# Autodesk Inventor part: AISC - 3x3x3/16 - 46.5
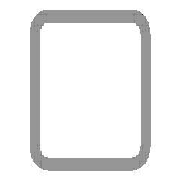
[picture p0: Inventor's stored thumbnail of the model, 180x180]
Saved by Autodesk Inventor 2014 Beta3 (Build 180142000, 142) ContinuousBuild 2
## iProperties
IsCustomPart: 1
Created: 2011-01
Part Number: AISC - 3x3x3/16 - 46.5
Material: Steel, Mild
Description: Tube
Document SubType Name: Modeling
Standard: ANSI
Designer: Beta-8540w
Standards Organization: ANSI
Language: en-US
Size Designation: 3x3x3/16
Categories: <MemberInstance><Categories><Category DisplayName="Structural Shapes" InternalName="089c4875-fa83-4c05-b084-43b9cc11f5ed" Mnemonic="GRDR"><CategoryParameter Dis
Stock Number: 3x3x3/16
Density: 7.86 g/cm^3
Appearance: Steel
_CCFamilyMember: 9
_CCFamilyDisplayName: ANSI AISC (Square) - Tube
_FrameMemberDoc: Frame Member File
_Version: 15.0.0
_GetPNFromCC: 1
G_W: 3.000 in
G_H: 3.000 in
G_L: 46.500 in
+C42BEBB0-0B1A-4817-9F77-B09BD408BF7C+CUTDETAIL2: Notch
Author: Beta-8540w
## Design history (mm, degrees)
node "Start plane"
node "End plane"
sketch "Sketch"
  geometry: L1 (-38.1, -28.575)-(-38.1, 28.575); L2 (-28.575, 38.1)-(28.575, 38.1); L3 (38.1, 28.575)-(38.1, -28.575); L4 (28.575, -38.1)-(-28.575, -38.1); L5 (-28.575, 33.337)-(28.575, 33.338); L6 (33.338, 28.575)-(33.338, -28.575); L7 (28.575, -33.337)-(-28.575, -33.338); L8 (-33.338, -28.575)-(-33.338, 28.575); L9 (0, 56.102)-(0, -56.102) reference; L10 (-56.102, 0)-(56.102, 0) reference; A1 r 9.525 centre (-28.575, -28.575) between (-38.1, -28.575) and (-28.575, -38.1); A2 r 9.525 centre (-28.575, 28.575) between (-28.575, 38.1) and (-38.1, 28.575); A3 r 9.525 centre (28.575, 28.575) between (38.1, 28.575) and (28.575, 38.1); A4 r 9.525 centre (28.575, -28.575) between (28.575, -38.1) and (38.1, -28.575); A5 r 4.763 centre (-28.575, 28.575) between (-28.575, 33.337) and (-33.338, 28.575); A6 r 4.763 centre (28.575, 28.575) between (33.338, 28.575) and (28.575, 33.338); A7 r 4.763 centre (28.575, -28.575) between (28.575, -33.337) and (33.338, -28.575); A8 r 4.763 centre (-28.575, -28.575) between (-33.338, -28.575) and (-28.575, -33.338)
  constraints: 16 end point, 16 point on circle, 8 centre point, 8 tangent, 4 parallel, 3 equal radius, 2 perpendicular, 7 other
  dimensions: "d10" = 76.2 distance between parallel lines of L2 L4 (= G_H); "d11" = 76.2 distance between parallel lines of L1 L3 (= G_W); "d12" = 4.7625 distance between parallel lines of L3 L6 (= G_T); "d15" = 38.1 distance between parallel lines of L2 L10 (= 0.5 x d10); "d16" = 38.1 distance between parallel lines of L9 L3 (= 0.5 x d11); "d17" = 9.525 radius of A1 (= G_IR)
extrude "Body" new body sketch "Sketch" stored distance "d3" = 1181.1 (= G_L); taper "d4" = 0 deg
node "Driven Length"
  sketch "Sketch3"
    geometry: L1 (0, 0)-(10, 0) reference
    constraints: 2 end point, 1 horizontal
  workplane "Work Plane3"
  sketch "Sketch4"
    geometry: L1 (-2, 38.1)-(12, 38.1) reference; L2 (-2, 1219.2)-(12, 1219.2) reference
    dimensions: "d19" = 1181.1 distance between parallel lines of L1 L2 (derived)
workplane "Work Plane4"
split "Split1"
body "Solid1"
feature "Sculpt1"
combine "Combine1"
body "Srf11"
body "Srf12"
body "Solid5"
feature "Surface1"
body "Srf10"
patch "Boundary Patch7" dims "d76" = 5, "d77" = 5, "d78" = 5, "d79" = 5, "d80" = 5, "d81" = 5, "d82" = 5, "d83" = 5, "d84" = 0
patch "Boundary Patch8" dims "d85" = 5, "d86" = 5, "d87" = 5, "d88" = 5, "d89" = 5, "d90" = 5, "d91" = 5, "d92" = 5, "d93" = 0
other parameters: "G_W" = 76.2 [user parameter; used in 1 equation term], "G_H" = 76.2 [user parameter; used in 1 equation term], "G_T" = 4.7625 [user parameter; used in 1 equation term], "G_IR" = 9.525 [user parameter; used in 1 equation term], "G_L" = 1181.1 (= d19) [user parameter; used in 1 equation term], "G_OFFSET_START" = -38.1 [user parameter; used in 1 equation term], "G_OFFSET_END" = 0 [user parameter; used in 1 equation term], "d13" = 38.1 (= -G_OFFSET_START), "d14" = 1219.2 (= G_OFFSET_END + B_L), "B_L" = 1219.2 [user parameter; used in 1 equation term], "d18" = 90 deg
